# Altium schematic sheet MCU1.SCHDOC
size B; Organization: Altium Limited; Address1: L3, 12a Rodborough Rd; Address2: Frenchs Forest; Address3: NSW; Address4: Australia 2086
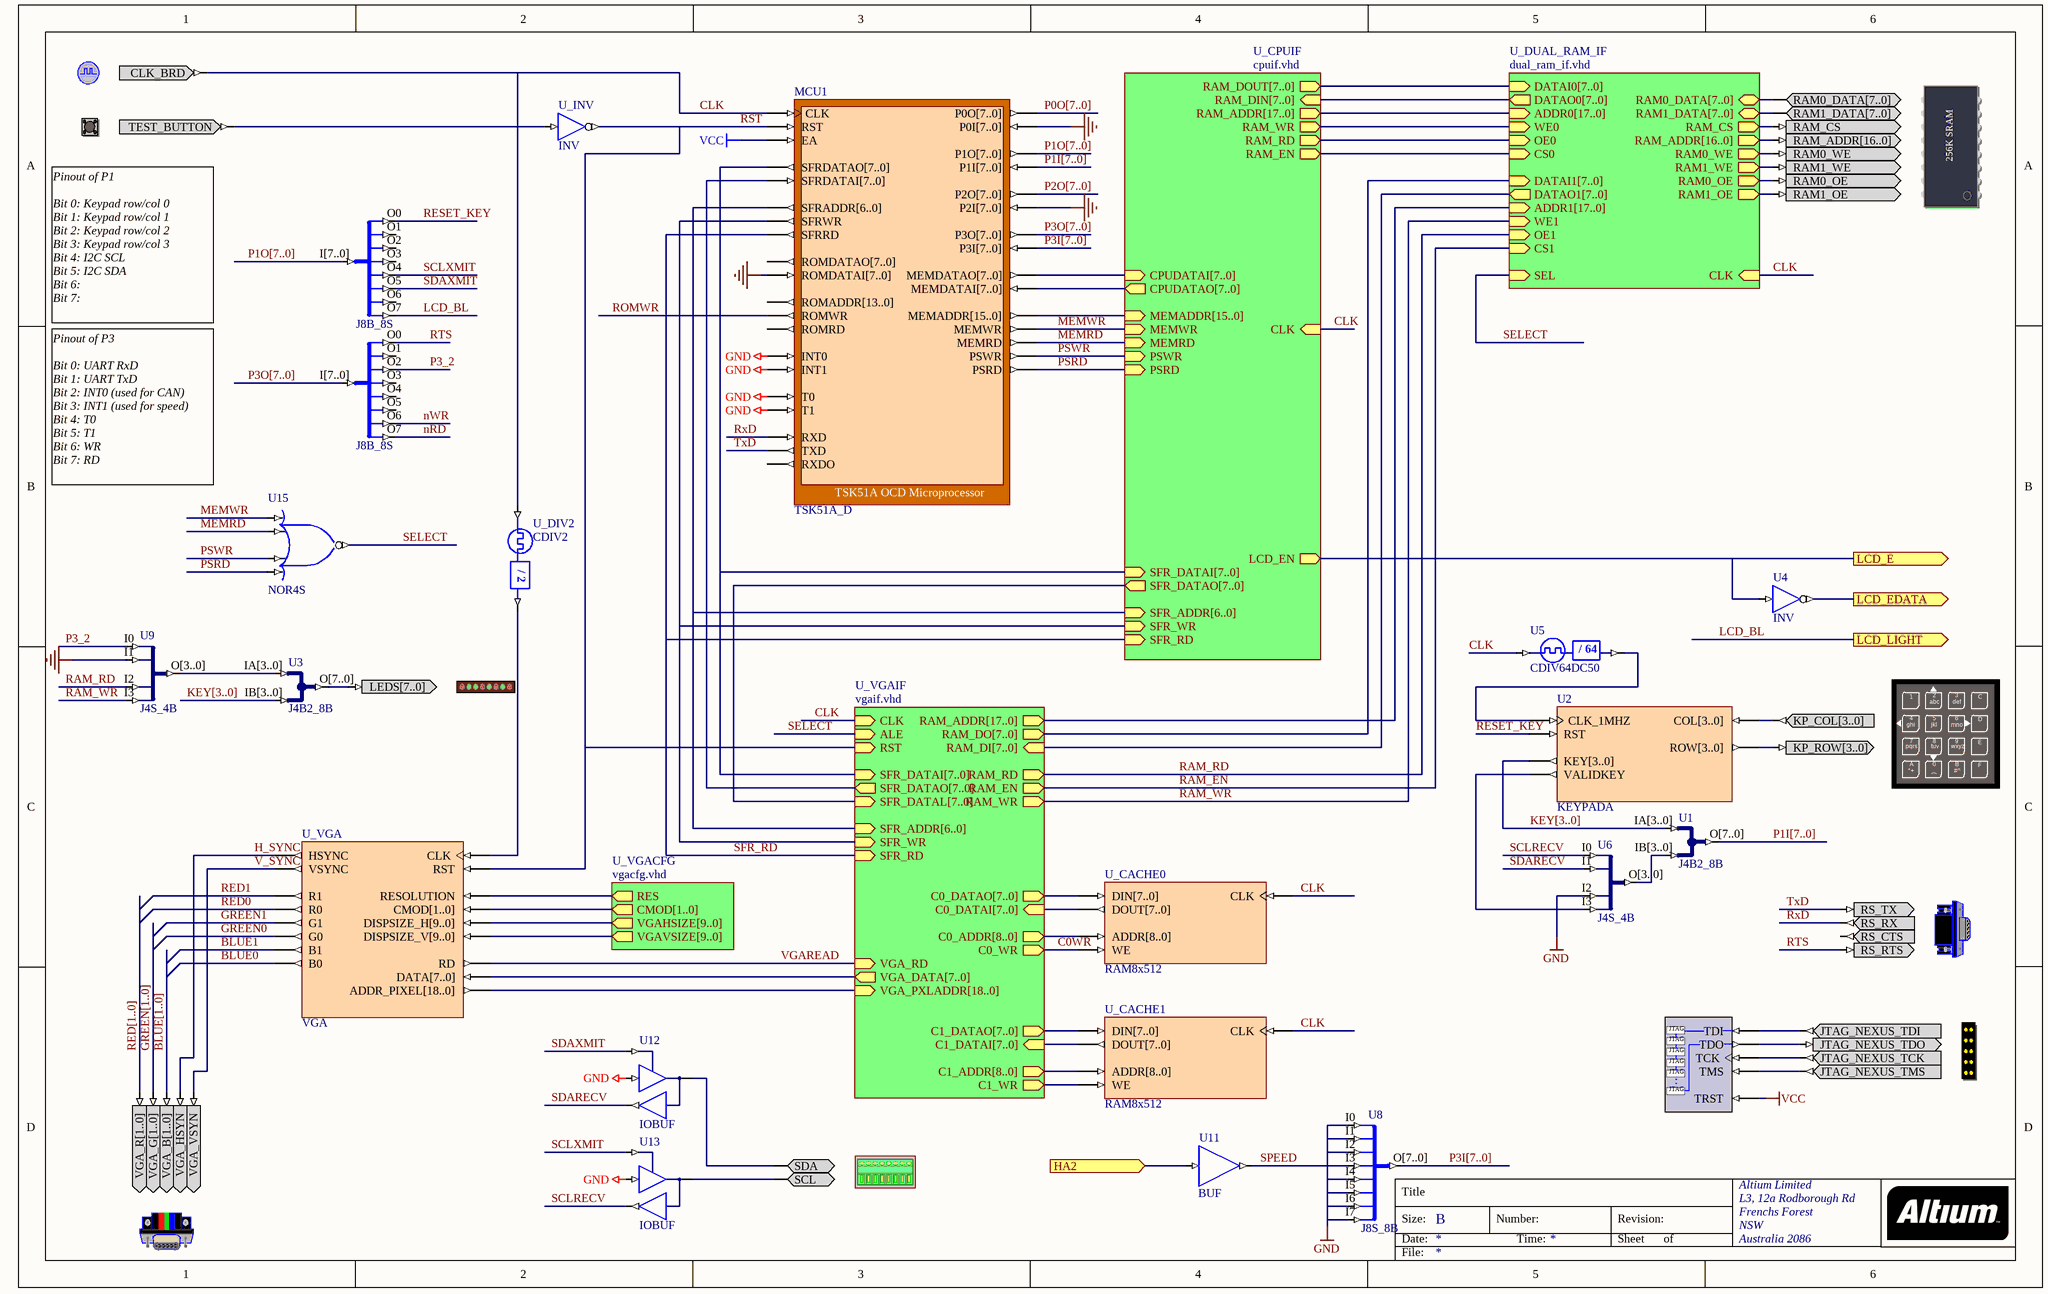
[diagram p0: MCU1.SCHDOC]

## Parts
(Parts that share a designator on the sheet are numbered #1, #2 ... from top to bottom, then left to right.)
?#1  CLOCK_BOARD  (value not drawn)
?#2  MEMORY256KX8  (value not drawn)
?#3  TEST_BUTTON  (value not drawn)
?#4  LED  (value not drawn)
?#5  KEYPAD  (value not drawn)
?#6  RS232CNTR  (value not drawn)
?#7  NEXUS_JTAG_PORT  (value not drawn)
?#8  NEXUS_JTAG_CONNECTOR  (value not drawn)
?#9  ADCDAC_I2C  (value not drawn)
?#10  VGACNTR  (value not drawn)
MCU1  TSK51A_D
U1  J4B2_8B
U2  KEYPADA
U3  J4B2_8B
U4  INV
U5  CDIV64DC50
U6  J4S_4B
U7  J8B_8S
U8  J8S_8B
U9  J4S_4B
U11  BUF
U12  IOBUF
U13  IOBUF
U15  NOR4S
U18  J8B_8S
U_CACHE0  RAM8x512
U_CACHE1  RAM8x512
U_DIV2  CDIV2
U_INV  INV
U_VGA  VGA

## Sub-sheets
U_CPUIF = cpuif.vhd: MEMWR (in), RAM_EN (out), RAM_WR (out), RAM_RD (out), RAM_DOUT[7..0] (out), MEMRD (in), LCD_EN (out), RAM_ADDR[17..0] (out), CLK (in), SFR_ADDR[6..0] (in), SFR_DATAI[7..0] (in), SFR_DATAO[7..0] (out), SFR_WR (in), SFR_RD (in), RAM_DIN[7..0] (in), PSWR (in), PSRD (in), MEMADDR[15..0] (in), CPUDATAI[7..0] (in), CPUDATAO[7..0] (out)
U_DUAL_RAM_IF = dual_ram_if.vhd: DATAI0[7..0] (in), DATAI1[7..0] (in), DATAO0[7..0] (out), DATAO1[7..0] (out), ADDR0[17..0] (in), ADDR1[17..0] (in), WE0 (in), WE1 (in), OE0 (in), OE1 (in), CS0 (in), CS1 (in), SEL (in), RAM0_DATA[7..0] (bidir), RAM1_DATA[7..0] (bidir), RAM_ADDR[16..0] (out), RAM0_WE (out), RAM1_WE (out), RAM0_OE (out), RAM1_OE (out), RAM_CS (out), CLK (in)
U_VGACFG = vgacfg.vhd: RES (out), CMOD[1..0] (out), VGAHSIZE[9..0] (out), VGAVSIZE[9..0] (out)
U_VGAIF = vgaif.vhd: VGA_PXLADDR[18..0] (in), VGA_DATA[7..0] (out), VGA_RD (in), C1_WR (out), C1_ADDR[8..0] (out), C1_DATAI[7..0] (in), C1_DATAO[7..0] (out), C0_WR (out), C0_ADDR[8..0] (out), C0_DATAI[7..0] (in), C0_DATAO[7..0] (out), RAM_ADDR[17..0] (out), CLK (in), ALE (in), RAM_DO[7..0] (out), RAM_RD (out), RAM_EN (out), RAM_WR (out), SFR_ADDR[6..0] (in), SFR_DATAI[7..0] (in), SFR_DATAO[7..0] (out), SFR_WR (in), SFR_RD (in), SFR_DATAL[7..0] (in), RAM_DI[7..0] (in), RST (in)

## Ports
HA2 (in), LCD_E (out), LCD_EDATA (out), LCD_LIGHT (out)

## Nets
GND: MCU1.INT0 MCU1.INT1 MCU1.T0 MCU1.T1 U6.I2 U8.I0 U8.I1 U8.I2 U8.I4 U8.I5 U8.I6 U8.I7 U9.I1 U12.I U13.I
VCC: ?#7.TRST MCU1.EA
BLUE0: U_VGA.B0
BLUE1: U_VGA.B1
C0WR: U_CACHE0.WE ; sheet U_VGAIF/C0_WR
CLK: ?#1.CLK_BRD MCU1.CLK U5.CLKIN U_CACHE0.CLK U_CACHE1.CLK U_DIV2.CLKIN ; sheet U_CPUIF/CLK, sheet U_VGAIF/CLK, sheet U_DUAL_RAM_IF/CLK
GREEN0: U_VGA.G0
GREEN1: U_VGA.G1
H_SYNC: ?#10.VGA_HSYN U_VGA.HSYNC
HA2: U11.I ; port HA2
LCD_BL: U18.O7 ; port LCD_LIGHT
LCD_E: U4.I ; port LCD_E, sheet U_CPUIF/LCD_EN
LCD_EDATA: U4.O ; port LCD_EDATA
MEMRD: MCU1.MEMRD U15.I1 ; sheet U_CPUIF/MEMRD
MEMWR: MCU1.MEMWR U15.I0 ; sheet U_CPUIF/MEMWR
nRD: U7.O7
nWR: U7.O6
P3_2: U7.O2 U9.I0
PSRD: MCU1.PSRD U15.I3 ; sheet U_CPUIF/PSRD
PSWR: MCU1.PSWR U15.I2 ; sheet U_CPUIF/PSWR
RAM_EN: sheet U_VGAIF/RAM_EN, sheet U_DUAL_RAM_IF/CS1
RAM_RD: U9.I2 ; sheet U_VGAIF/RAM_RD, sheet U_DUAL_RAM_IF/OE1
RAM_WR: U9.I3 ; sheet U_VGAIF/RAM_WR, sheet U_DUAL_RAM_IF/WE1
RED0: U_VGA.R0
RED1: U_VGA.R1
RESET_KEY: U2.RST U18.O0
ROMWR: MCU1.ROMWR
RST: MCU1.RST U_INV.O U_VGA.RST ; sheet U_VGAIF/RST
RTS: ?#6.RS_RTS U7.O0
RxD: ?#6.RS_RX MCU1.RXD
SCLRECV: U6.I0 U13.O
SCLXMIT: U13.T U18.O4
SDARECV: U6.I1 U12.O
SDAXMIT: U12.T U18.O5
SELECT: U15.O ; sheet U_VGAIF/ALE, sheet U_DUAL_RAM_IF/SEL
SFR_RD: MCU1.SFRRD ; sheet U_CPUIF/SFR_RD, sheet U_VGAIF/SFR_RD
SPEED: U8.I3 U11.O
TxD: ?#6.RS_TX MCU1.TXD
V_SYNC: ?#10.VGA_VSYN U_VGA.VSYNC
VGAREAD: U_VGA.RD ; sheet U_VGAIF/VGA_RD
Net?#2_RAM0_OE: ?#2.RAM0_OE ; sheet U_DUAL_RAM_IF/RAM0_OE
Net?#2_RAM0_WE: ?#2.RAM0_WE ; sheet U_DUAL_RAM_IF/RAM0_WE
Net?#2_RAM1_OE: ?#2.RAM1_OE ; sheet U_DUAL_RAM_IF/RAM1_OE
Net?#2_RAM1_WE: ?#2.RAM1_WE ; sheet U_DUAL_RAM_IF/RAM1_WE
Net?#2_RAM_CS: ?#2.RAM_CS ; sheet U_DUAL_RAM_IF/RAM_CS
Net?#3_TEST_BUTTON: ?#3.TEST_BUTTON U_INV.I
Net?#7_TCK: ?#7.TCK ?#8.JTAG_NEXUS_TCK
Net?#7_TDI: ?#7.TDI ?#8.JTAG_NEXUS_TDI
Net?#7_TDO: ?#7.TDO ?#8.JTAG_NEXUS_TDO
Net?#7_TMS: ?#7.TMS ?#8.JTAG_NEXUS_TMS
Net?#9_SCL: ?#9.SCL U13.IO
Net?#9_SDA: ?#9.SDA U12.IO
NetMCU1_SFRWR: MCU1.SFRWR ; sheet U_CPUIF/SFR_WR, sheet U_VGAIF/SFR_WR
NetU2_CLK_1MHZ: U2.CLK_1MHZ U5.CLKDV
NetU2_VALIDKEY: U2.VALIDKEY U6.I3
NetU_CACHE1_WE: U_CACHE1.WE ; sheet U_VGAIF/C1_WR
NetU_DIV2_CLKDV: U_DIV2.CLKDV U_VGA.CLK
NetU_VGA_RESOLUTION: U_VGA.RESOLUTION ; sheet U_VGACFG/RES
(unnamed): sheet U_CPUIF/RAM_EN, sheet U_DUAL_RAM_IF/CS0
(unnamed): sheet U_CPUIF/RAM_WR, sheet U_DUAL_RAM_IF/WE0  [a separate net that carries the same name]
(unnamed): sheet U_CPUIF/RAM_RD, sheet U_DUAL_RAM_IF/OE0  [a separate net that carries the same name]

Not connected (* = marked no-connect by the designer): ?#2 RAM0_DATA[7..0] RAM1_DATA[7..0] RAM_ADDR[16..0]; ?#4 LEDS[7..0]; ?#5 KP_COL[3..0] KP_ROW[3..0]; ?#6 RS_CTS; ?#10 VGA_B[1..0] VGA_G[1..0] VGA_R[1..0]; MCU1 MEMADDR[15..0] MEMDATAI[7..0] MEMDATAO[7..0] P0I[7..0] P0O[7..0] P1I[7..0] P1O[7..0] P2I[7..0] P2O[7..0] P3I[7..0] P3O[7..0] ROMADDR[13..0] ROMDATAI[7..0] ROMDATAO[7..0] ROMRD RXDO SFRADDR[6..0] SFRDATAI[7..0] SFRDATAO[7..0]; U1 IA[3..0] IB[3..0] O[7..0]; U2 COL[3..0] KEY[3..0] ROW[3..0]; U3 IA[3..0] IB[3..0] O[7..0]; U6 O[3..0]; U7 I[7..0] O1 O3 O4 O5; U8 O[7..0]; U9 O[3..0]; U18 I[7..0] O1 O2 O3 O6; U_CACHE0 ADDR[8..0] DIN[7..0] DOUT[7..0]; U_CACHE1 ADDR[8..0] DIN[7..0] DOUT[7..0]; U_VGA ADDR_PIXEL[18..0] CMOD[1..0] DATA[7..0] DISPSIZE_H[9..0] DISPSIZE_V[9..0]

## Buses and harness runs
bus BLUE[1..0]
bus GREEN[1..0]
bus KEY[3..0]
bus P0O[7..0]
bus P1I[7..0]
bus P1O[7..0]
bus P2O[7..0]
bus P3I[7..0]
bus P3O[7..0]
bus RED[1..0]
bus sheet U_CPUIF/RAM_ADDR[17..0] = sheet U_DUAL_RAM_IF/ADDR0[17..0]
bus sheet U_CPUIF/RAM_DIN[7..0] = sheet U_DUAL_RAM_IF/DATAO0[7..0]
bus sheet U_CPUIF/RAM_DOUT[7..0] = sheet U_DUAL_RAM_IF/DATAI0[7..0]
bus sheet U_CPUIF/SFR_ADDR[6..0] = sheet U_VGAIF/SFR_ADDR[6..0]
bus sheet U_CPUIF/SFR_DATAI[7..0] = sheet U_VGAIF/SFR_DATAI[7..0]
bus sheet U_CPUIF/SFR_DATAO[7..0] = sheet U_VGAIF/SFR_DATAL[7..0]
bus sheet U_DUAL_RAM_IF/ADDR1[17..0] = sheet U_VGAIF/RAM_ADDR[17..0]
bus sheet U_DUAL_RAM_IF/DATAI1[7..0] = sheet U_VGAIF/RAM_DO[7..0]
bus sheet U_DUAL_RAM_IF/DATAO1[7..0] = sheet U_VGAIF/RAM_DI[7..0]

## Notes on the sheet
- Pinout of P1
  Bit 0: Keypad row/col 0
  Bit 1: Keypad row/col 1
  Bit 2: Keypad row/col 2
  Bit 3: Keypad row/col 3
  Bit 4: I2C SCL
  Bit 5: I2C SDA
  Bit 6:
  Bit 7:
- Pinout of P3
  Bit 0: UART RxD
  Bit 1: UART TxD
  Bit 2: INT0 (used for CAN)
  Bit 3: INT1 (used for speed)
  Bit 4: T0
  Bit 5: T1
  Bit 6: WR
  Bit 7: RD
- Labels drawn without touching a wire or pin: GNDBUS[..]

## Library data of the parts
?#1 = CLOCK_BOARD: Global System Clock Supply; PortComponent: True
?#2 = MEMORY256KX8: SRAM 256kx8; PortComponent: True
?#3 = TEST_BUTTON: Test Button; PortComponent: True
?#4 = LED: 8-Way LEDS; PortComponent: True
?#5 = KEYPAD: Key Pad; PortComponent: True
?#6 = RS232CNTR: DCE Serial Port Connector; PortComponent: True
?#7 = NEXUS_JTAG_PORT: Nexus Processor JTAG Chain Connector; NEXUS_JTAG_CONNECTOR: True
?#8 = NEXUS_JTAG_CONNECTOR: JTAG Port; PortComponent: True
?#9 = ADCDAC_I2C: Analog Digital/ Digital Analog Converter, I2C Interface; PortComponent: True
?#10 = VGACNTR: VGA Dsub-15-Female-HD; PortComponent: True
MCU1 = TSK51A_D: TSK51A OCD Microprocessor; NEXUS_CORE: Processor_OCDS; NEXUS_JTAG_DEVICE: True; NEXUS_JTAG_ORDER: 0; ChildModel1: RAM256x8_TSK51D
U1 U3 = J4B2_8B: 2 x 4-Bit input bus to 1 x 8-bit output bus; Class I: Bus Joiner; ArchiveName: GENERIC
U2 = KEYPADA: Keypad
U4 U_INV = INV: Inverter; Class I: Logic Primitive; ArchiveName: GENERIC
U5 = CDIV64DC50: Clock Divider by 64 with 50% Duty Cycle Output; ArchiveName: GENERIC
U6 U9 = J4S_4B: 4 Single pin inputs to single 4-Bit output bus; Class I: Bus Joiner; ArchiveName: GENERIC
U7 U18 = J8B_8S: 8-Bit input bus to 8 single pin outputs; Class I: Bus Joiner; ArchiveName: GENERIC
U8 = J8S_8B: 8 Single pin inputs to single 8-Bit output bus; Class I: Bus Joiner; ArchiveName: GENERIC
U11 = BUF: Buffer; ArchiveName: GENERIC
U12 U13 = IOBUF: Input/Output Buffer; ArchiveName: GENERIC
U15 = NOR4S: 4-Input NOR Gate, Single Pin Version; Xilinx Equivalent: NOR4; ArchiveName: GENERIC
U_CACHE0 U_CACHE1 = RAM8x512: Single Port Random Access Memory 512 x 8; Memory_Depth: 512; Memory_Type: RAM_SinglePortBlock; Memory_Width: 8; Memory_ClockEdge: Rising; Nexus_Core: Memory_Program
U_DIV2 = CDIV2: Clock Divider by 2; ArchiveName: GENERIC
U_VGA = VGA: VGA Controller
